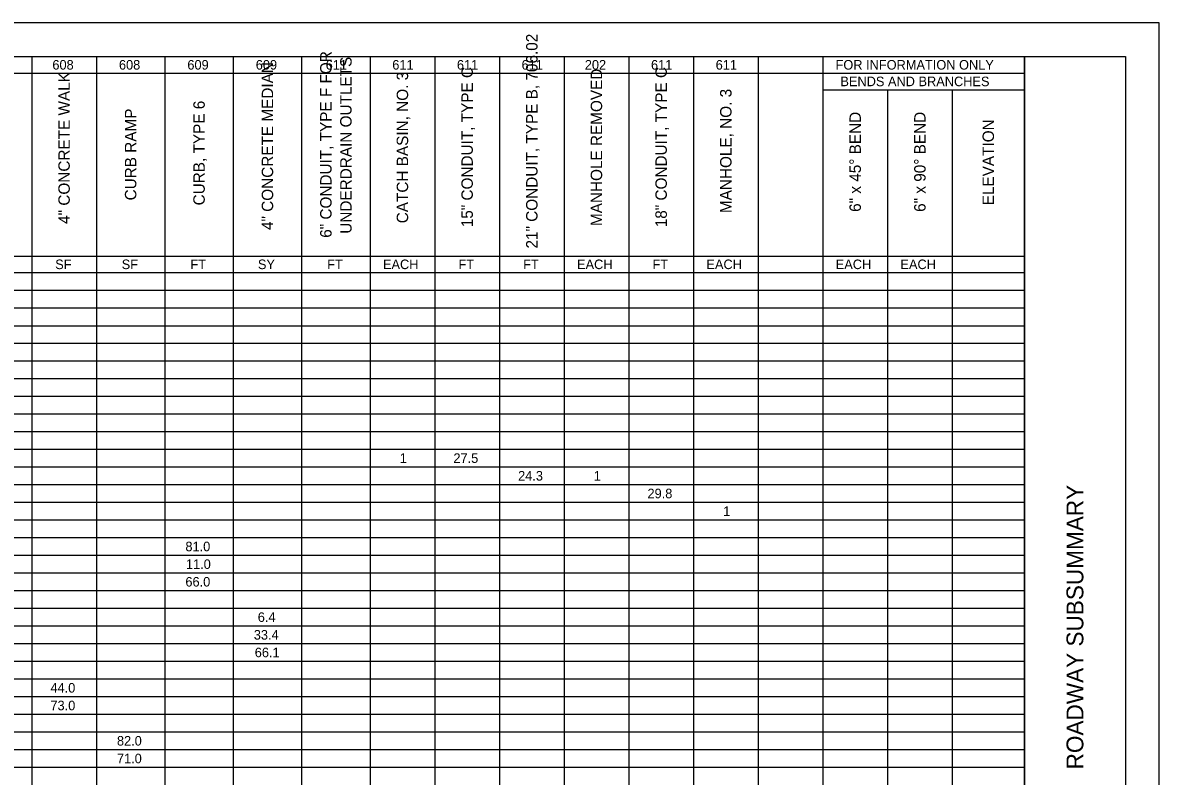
# Model space of a CAD drawing. Extents: x 0 to 34, y 0 to 22.
# Drawn here: x 17.15 to 34, y 10.84 to 22 of the extents above; entities that cross this region are included whole.
import ezdxf

# ---------------------------------------------------------------- set-up
doc = ezdxf.new("R2010")
doc.units = 0
for name, color, linetype in [('SH_Border', 7, 'Continuous'), ('SH_Cut_Line', 7, 'Continuous'), ('SH_Data', 7, 'Continuous'), ('SH_Text', 7, 'Continuous')]:
    doc.layers.add(name, color=color, linetype=linetype)

msp = doc.modelspace()

# ---------------------------------------------------------------- linework, layer by layer
at = {"layer": 'SH_Border'}
msp.add_line((32, 0.5), (32, 21.5), dxfattribs=at)
msp.add_lwpolyline([(1.5, 21.5), (33.5, 21.5), (33.5, 0.5), (1.5, 0.5)], close=True, dxfattribs=at)
at = {"layer": 'SH_Cut_Line'}
msp.add_lwpolyline([(0, 0), (34, 0), (34, 22), (0, 22)], close=True, dxfattribs=at)
at = {"layer": 'SH_Text'}
for p, q in [((1.5, 21.5), (32, 21.5)), ((17.285, 21.5), (17.285, 0.5)), ((18.244, 21.5), (18.244, 0.5)), ((19.258, 21.5), (19.258, 0.5)), ((20.272, 21.5), (20.272, 0.5)), ((21.286, 21.5), (21.286, 0.5)), ((22.3, 21.5), (22.3, 0.5)), ((23.259, 21.5), (23.259, 0.5)), ((24.218, 21.5), (24.218, 0.5)), ((25.177, 21.5), (25.177, 0.5)), ((26.136, 21.5), (26.136, 0.5)), ((27.095, 21.5), (27.095, 0.5)), ((28.054, 21.5), (28.054, 0.5)), ((29.013, 21.5), (29.013, 0.5)), ((32, 21.5), (32, 0.5)), ((10.573, 21.254), (32, 21.254)), ((29.013, 21.007), (32, 21.007)), ((29.972, 21.007), (29.972, 0.5)), ((30.93, 21.007), (30.93, 0.5)), ((10.573, 18.544), (32, 18.544)), ((1.5, 18.298), (32, 18.298)), ((1.5, 18.036), (32, 18.036)), ((1.5, 17.774), (32, 17.774)), ((1.5, 17.512), (32, 17.512)), ((1.5, 17.251), (32, 17.251)), ((1.5, 16.989), (32, 16.989)), ((1.5, 16.727), (32, 16.727)), ((1.5, 16.466), (32, 16.466)), ((1.5, 16.204), (32, 16.204)), ((1.5, 15.942), (32, 15.942)), ((1.5, 15.68), (32, 15.68)), ((1.5, 15.419), (32, 15.419)), ((1.5, 15.157), (32, 15.157)), ((1.5, 14.895), (32, 14.895)), ((1.5, 14.633), (32, 14.633)), ((1.5, 14.372), (32, 14.372)), ((1.5, 14.11), (32, 14.11)), ((1.5, 13.848), (32, 13.848)), ((1.5, 13.587), (32, 13.587)), ((1.5, 13.325), (32, 13.325)), ((1.5, 13.063), (32, 13.063)), ((1.5, 12.801), (32, 12.801)), ((1.5, 12.54), (32, 12.54)), ((1.5, 12.278), (32, 12.278)), ((1.5, 12.016), (32, 12.016)), ((1.5, 11.754), (32, 11.754)), ((1.5, 11.493), (32, 11.493)), ((1.5, 11.231), (32, 11.231)), ((1.5, 10.969), (32, 10.969))]:
    msp.add_line(p, q, dxfattribs=at)

# ---------------------------------------------------------------- texts
at = {"layer": 'SH_Data'}
msp.add_text('ROADWAY SUBSUMMARY', height=0.25, rotation=90, dxfattribs=at).set_placement((32.875, 10.938))
at = {"layer": 'SH_Text'}
for s, height, p in [('21" CONDUIT, TYPE B, 706.02', 0.16965, (24.783, 18.655)), ('6" CONDUIT, TYPE F FOR ', 0.16965, (21.73, 18.814)), ('4" CONCRETE MEDIAN', 0.16965, (20.864, 18.929)), ('UNDERDRAIN OUTLETS', 0.16965, (22.027, 18.874)), ('4" CONCRETE WALK', 0.16965, (17.849, 19.02)), ('CATCH BASIN, NO. 3', 0.16965, (22.865, 19.029)), ('15" CONDUIT, TYPE C', 0.16965, (23.824, 18.97)), ('MANHOLE REMOVED', 0.16965, (25.741, 18.988)), ('18" CONDUIT, TYPE C', 0.16965, (26.7, 18.97)), ('MANHOLE, NO. 3', 0.16965, (27.659, 19.18)), ('CURB, TYPE 6', 0.16965, (19.85, 19.294)), ('CURB RAMP', 0.1696, (18.836, 19.368)), ('6" x 45° BEND', 0.16965, (29.577, 19.198)), ('6" x 90° BEND', 0.16965, (30.536, 19.198)), ('ELEVATION', 0.1696, (31.55, 19.296))]:
    msp.add_text(s, height=height, rotation=90, dxfattribs=at).set_placement(p)
for s, height, p in [('608', 0.1416, (17.591, 21.306)), ('608', 0.1416, (18.578, 21.306)), ('609', 0.1416, (19.592, 21.306)), ('609', 0.1416, (20.606, 21.306)), ('611', 0.1416, (21.643, 21.306)), ('611', 0.1416, (22.63, 21.306)), ('611', 0.1416, (23.588, 21.306)), ('611', 0.1416, (24.547, 21.306)), ('202', 0.1416, (25.484, 21.306)), ('611', 0.1416, (26.465, 21.306)), ('611', 0.1416, (27.424, 21.306)), ('FOR INFORMATION ONLY', 0.14164, (29.201, 21.306)), ('BENDS AND BRANCHES', 0.14164, (29.273, 21.06)), ('SF', 0.1416, (17.633, 18.35)), ('SF', 0.1416, (18.619, 18.35)), ('FT', 0.1416, (19.637, 18.35)), ('SY', 0.1416, (20.638, 18.35)), ('FT', 0.1416, (21.665, 18.35)), ('EACH', 0.1416, (22.492, 18.35)), ('FT', 0.1416, (23.611, 18.35)), ('FT', 0.1416, (24.57, 18.35)), ('EACH', 0.1416, (25.369, 18.35)), ('FT', 0.1416, (26.487, 18.35)), ('EACH', 0.1416, (27.287, 18.35)), ('EACH', 0.1416, (29.204, 18.35)), ('EACH', 0.1416, (30.163, 18.35)), ('1', 0.142, (22.74, 15.479)), ('27.5', 0.1416, (23.536, 15.479)), ('24.3', 0.1416, (24.495, 15.217)), ('1', 0.142, (25.617, 15.217)), ('29.8', 0.1416, (26.413, 14.955)), ('1', 0.142, (27.535, 14.693)), ('81.0', 0.1416, (19.563, 14.17)), ('11.0', 0.1416, (19.571, 13.908)), ('66.0', 0.1416, (19.563, 13.647)), ('6.4', 0.1416, (20.636, 13.123)), ('33.4', 0.1416, (20.577, 12.861)), ('66.1', 0.1416, (20.591, 12.6)), ('44.0', 0.1416, (17.562, 12.076)), ('73.0', 0.1416, (17.562, 11.814)), ('82.0', 0.1416, (18.548, 11.291)), ('71.0', 0.1416, (18.548, 11.029))]:
    msp.add_text(s, height=height, dxfattribs=at).set_placement(p)

doc.saveas('drawing.dxf')
